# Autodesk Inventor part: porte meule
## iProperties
Shininess: 64.0
Length Units: 11269
Angle Units: 11279
Time Units: 11290
Mass Units: 11283
Length Display Precision: 3
Angle Display Precision: 2
Compacted: True
Part Number: porte meule
Document SubType Name: Modeling
Created: 2005-01
Material: Par défaut
Designer: LEGERET Philippe
Density: 0.0
Volumn: 0.0
Area: 0.0
PropertySet Name: Model Information
Control State: 0
Master: False
Checked Out: False
Author: LEGERET Philippe
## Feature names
1. Extrusion1
2. Extrusion2
3. Perçage1 [Hole]
4. Réseau circulaire1 [Circular Pattern]
